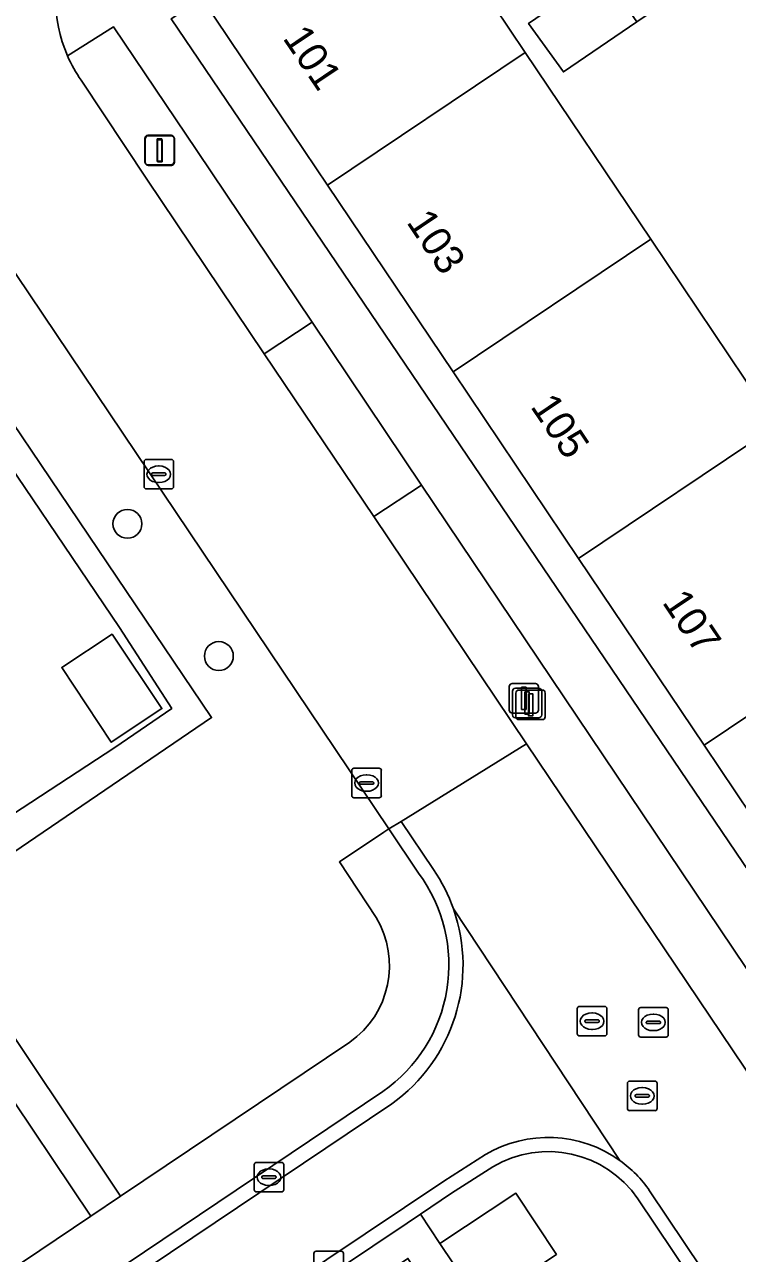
# Model space of a CAD drawing. Extents: x 158793 to 159888, y 384317 to 385256.
# Drawn here: x 159112.15 to 159136.27, y 384672.74 to 384714.36 of the extents above; entities that cross this region are included whole.
import ezdxf

# ---------------------------------------------------------------- set-up
doc = ezdxf.new("R2010")
doc.units = 0
for name, color, linetype in [('IMGEO_Berm_groen', 7, 'Continuous'), ('IMGEO_Boom', 7, 'Continuous'), ('IMGEO_Erf', 7, 'Continuous'), ('IMGEO_Groenvoorziening', 7, 'Continuous'), ('IMGEO_Haag', 7, 'Continuous'), ('IMGEO_Kolk', 7, 'Continuous'), ('IMGEO_Lichtmast', 7, 'Continuous'), ('IMGEO_Pand', 7, 'Continuous'), ('IMGEO_Pand_nummerreeks', 7, 'Continuous'), ('IMGEO_Parkeervlak_halfverhard', 7, 'Continuous'), ('IMGEO_Rijbaan_lokaal_open', 7, 'Continuous'), ('IMGEO_Rioolput', 7, 'Continuous'), ('IMGEO_Voetpad_halfverhard', 7, 'Continuous'), ('IMGEO_Voetpad_open', 7, 'Continuous')]:
    doc.layers.add(name, color=color, linetype=linetype)

msp = doc.modelspace()

# ---------------------------------------------------------------- linework, layer by layer
at = {"layer": 'IMGEO_Berm_groen'}
for points in [[(159115.157, 384714.276), (159113.6, 384713.295)], [(159114.065, 384712.473), (159116.285, 384709.123), (159120.258, 384703.211), (159121.876, 384704.284), (159117.976, 384710.09), (159115.157, 384714.276)], [(159125.586, 384698.761), (159123.965, 384697.697), (159129.137, 384690.002), (159138.056, 384676.732)], [(159141.53, 384675.048), (159141.397, 384675.222), (159125.586, 384698.761)], [(159127.995, 384675.679), (159126.599, 384674.78), (159125.549, 384674.076), (159126.206, 384673.075), (159128.775, 384674.779), (159130.148, 384672.707), (159127.589, 384671.004), (159136.246, 384658.77), (159136.871, 384659.186), (159139.241, 384655.885)], [(159143.015, 384659.487), (159142.977, 384659.569), (159132.904, 384674.594)]]:
    msp.add_lwpolyline(points, dxfattribs=at)
for centre, radius, start, end in [((159117.908, 384715.189), 4.706, 203.7376, 215.2555), ((159129.868, 384672.507), 3.684, 34.5126, 120.5609)]:
    msp.add_arc(centre, radius, start, end, dxfattribs=at)
at = {"layer": 'IMGEO_Boom'}
for centre in [(159115.627, 384697.449), (159118.722, 384692.972)]:
    msp.add_circle(centre, 0.489, dxfattribs=at)
at = {"layer": 'IMGEO_Erf'}
for points in [[(159130.77, 384723.782), (159124.843, 384719.739), (159129.091, 384713.416), (159133.339, 384707.093), (159137.587, 384700.771), (159141.835, 384694.448), (159146.083, 384688.125), (159150.331, 384681.802), (159156.259, 384685.944)], [(159132.872, 384714.449), (159130.387, 384712.756), (159129.203, 384714.398), (159131.723, 384716.125), (159134.243, 384717.853), (159135.378, 384716.157)], [(159113.403, 384692.586), (159115.106, 384693.712), (159116.797, 384691.192), (159115.078, 384690.055)]]:
    msp.add_lwpolyline(points, close=True, dxfattribs=at)
msp.add_lwpolyline([(159108.265, 384685.338), (159115.197, 384689.875), (159117.127, 384691.2), (159115.361, 384693.939), (159105.215, 384708.932)], dxfattribs=at)
at = {"layer": 'IMGEO_Groenvoorziening'}
for points in [[(159103.077, 384713.871), (159105.954, 384709.447), (159118.478, 384690.888), (159108.91, 384684.374), (159115.398, 384674.683), (159123.154, 384679.895)], [(159118.478, 384690.888), (159105.954, 384709.447), (159103.077, 384713.871)], [(159102.092, 384713.443), (159100.643, 384712.514), (159093.526, 384707.69), (159093.829, 384707.184), (159094.623, 384707.728), (159097.156, 384709.402), (159102.429, 384713.049), (159105.215, 384708.932), (159115.361, 384693.939), (159117.127, 384691.2), (159115.197, 384689.875), (159108.265, 384685.338), (159108.91, 384684.374), (159118.478, 384690.888)], [(159124.044, 384684.121), (159122.802, 384686.002), (159124.307, 384687.004), (159124.478, 384687.124), (159108.697, 384710.581), (159107.572, 384712.264)], [(159114.386, 384674.002), (159107.906, 384683.665), (159099.356, 384678.075)], [(159097.742, 384678.578), (159096.312, 384680.64), (159079.482, 384669.508), (159079.569, 384669.376), (159079.588, 384669.39), (159080.687, 384667.744), (159085.364, 384670.862), (159087.614, 384667.53), (159092.976, 384659.587), (159114.386, 384674.002)]]:
    msp.add_lwpolyline(points, dxfattribs=at)
msp.add_lwpolyline([(159131.37, 384663.302), (159134.369, 384658.886), (159130.239, 384656.078), (159130.835, 384655.176), (159135.895, 384658.537), (159136.246, 384658.77), (159127.589, 384671.004), (159127.54, 384671.077), (159126.206, 384673.075), (159125.549, 384674.076), (159125.095, 384673.771), (159120.411, 384670.625), (159120.976, 384669.793), (159125.12, 384672.575), (159130.785, 384664.135), (159126.66, 384661.331), (159127.184, 384660.536)], close=True, dxfattribs=at)
msp.add_arc((159121.324, 384682.487), 3.173, 305.2214, 30.9931, dxfattribs=at)
at = {"layer": 'IMGEO_Haag'}
for points in [[(159118.478, 384690.888), (159105.954, 384709.447), (159103.077, 384713.871)], [(159102.092, 384713.443), (159100.643, 384712.514), (159093.526, 384707.69), (159093.829, 384707.184), (159094.623, 384707.728), (159097.156, 384709.402), (159102.429, 384713.049), (159105.215, 384708.932), (159115.361, 384693.939), (159117.127, 384691.2), (159115.197, 384689.875), (159108.265, 384685.338), (159108.91, 384684.374), (159118.478, 384690.888)]]:
    msp.add_lwpolyline(points, dxfattribs=at)
at = {"layer": 'IMGEO_Kolk'}
for p, q in [((159116.188, 384698.704), (159116.188, 384699.556)), ((159116.263, 384699.63), (159117.115, 384699.63)), ((159117.189, 384699.556), (159117.189, 384698.704)), ((159116.447, 384699.124), (159116.447, 384699.136)), ((159116.49, 384699.173), (159116.888, 384699.173)), ((159116.676, 384699.41), (159116.701, 384699.41)), ((159116.931, 384699.136), (159116.931, 384699.124)), ((159116.885, 384699.087), (159116.487, 384699.087)), ((159116.699, 384698.85), (159116.674, 384698.85)), ((159117.115, 384698.63), (159116.263, 384698.63)), ((159123.295, 384689.171), (159124.147, 384689.171)), ((159123.22, 384688.245), (159123.22, 384689.097)), ((159123.522, 384688.714), (159123.92, 384688.714)), ((159123.708, 384688.951), (159123.733, 384688.951)), ((159124.221, 384689.097), (159124.221, 384688.245)), ((159123.479, 384688.665), (159123.479, 384688.677)), ((159123.917, 384688.628), (159123.519, 384688.628)), ((159123.731, 384688.391), (159123.706, 384688.391)), ((159123.963, 384688.677), (159123.963, 384688.665)), ((159124.147, 384688.171), (159123.295, 384688.171)), ((159119.992, 384675.823), (159120.844, 384675.823)), ((159119.917, 384674.897), (159119.917, 384675.749)), ((159120.405, 384675.603), (159120.43, 384675.603)), ((159120.918, 384675.749), (159120.918, 384674.897)), ((159120.176, 384675.317), (159120.176, 384675.329)), ((159120.614, 384675.28), (159120.216, 384675.28)), ((159120.219, 384675.366), (159120.617, 384675.366)), ((159120.428, 384675.043), (159120.403, 384675.043)), ((159120.66, 384675.329), (159120.66, 384675.317)), ((159120.844, 384674.823), (159119.992, 384674.823)), ((159121.938, 384671.89), (159121.938, 384672.742)), ((159122.013, 384672.816), (159122.865, 384672.816)), ((159122.939, 384672.742), (159122.939, 384671.89))]:
    msp.add_line(p, q, dxfattribs=at)
for points in [[(159116.188, 384698.704), (159116.188, 384699.556)], [(159116.263, 384699.63), (159117.115, 384699.63)], [(159117.189, 384699.556), (159117.189, 384698.704)], [(159117.115, 384698.63), (159116.263, 384698.63)], [(159123.295, 384689.171), (159124.147, 384689.171)], [(159123.22, 384688.245), (159123.22, 384689.097)], [(159124.221, 384689.097), (159124.221, 384688.245)], [(159124.147, 384688.171), (159123.295, 384688.171)], [(159119.992, 384675.823), (159120.844, 384675.823)], [(159119.917, 384674.897), (159119.917, 384675.749)], [(159120.918, 384675.749), (159120.918, 384674.897)], [(159120.844, 384674.823), (159119.992, 384674.823)], [(159121.938, 384671.89), (159121.938, 384672.742)], [(159122.013, 384672.816), (159122.865, 384672.816)], [(159122.939, 384672.742), (159122.939, 384671.89)]]:
    msp.add_lwpolyline(points, dxfattribs=at)
for centre, radius, start, end in [((159116.265, 384699.554), 0.0765, 91.552, 178.448), ((159116.265, 384699.554), 0.0765, 91.552, 178.448), ((159117.113, 384699.554), 0.0765, 1.552, 88.448), ((159117.113, 384699.554), 0.0765, 1.552, 88.448), ((159116.487, 384699.133), 0.0403, 85.8775, 175.7526), ((159116.484, 384699.123), 0.0366, 178.938, 274.7102), ((159116.888, 384699.13), 0.043, 264.8664, 352.4533), ((159116.892, 384699.135), 0.0386, 1.7309, 96.639), ((159116.265, 384698.706), 0.0765, 181.552, 268.448), ((159116.265, 384698.706), 0.0765, 181.552, 268.448), ((159117.113, 384698.706), 0.0765, 271.552, 358.448), ((159117.113, 384698.706), 0.0765, 271.552, 358.448), ((159123.297, 384689.095), 0.0765, 91.552, 178.448), ((159123.297, 384689.095), 0.0765, 91.552, 178.448), ((159124.145, 384689.095), 0.0765, 1.552, 88.448), ((159124.145, 384689.095), 0.0765, 1.552, 88.448), ((159123.519, 384688.674), 0.0403, 85.8775, 175.7526), ((159123.924, 384688.676), 0.0386, 1.7309, 96.639), ((159123.516, 384688.664), 0.0366, 178.938, 274.7102), ((159123.92, 384688.671), 0.043, 264.8664, 352.4533), ((159123.297, 384688.247), 0.0765, 181.552, 268.448), ((159123.297, 384688.247), 0.0765, 181.552, 268.448), ((159124.145, 384688.247), 0.0765, 271.552, 358.448), ((159124.145, 384688.247), 0.0765, 271.552, 358.448), ((159119.994, 384675.747), 0.0765, 91.552, 178.448), ((159119.994, 384675.747), 0.0765, 91.552, 178.448), ((159120.842, 384675.747), 0.0765, 1.552, 88.448), ((159120.842, 384675.747), 0.0765, 1.552, 88.448), ((159120.216, 384675.326), 0.0403, 85.8775, 175.7526), ((159120.213, 384675.316), 0.0366, 178.938, 274.7102), ((159120.617, 384675.323), 0.043, 264.8664, 352.4533), ((159120.621, 384675.328), 0.0386, 1.7309, 96.639), ((159119.994, 384674.899), 0.0765, 181.552, 268.448), ((159119.994, 384674.899), 0.0765, 181.552, 268.448), ((159120.842, 384674.899), 0.0765, 271.552, 358.448), ((159120.842, 384674.899), 0.0765, 271.552, 358.448), ((159122.015, 384672.74), 0.0765, 91.552, 178.448), ((159122.015, 384672.74), 0.0765, 91.552, 178.448), ((159122.863, 384672.74), 0.0765, 1.552, 88.448), ((159122.863, 384672.74), 0.0765, 1.552, 88.448)]:
    msp.add_arc(centre, radius, start, end, dxfattribs=at)
for centre, major_axis, ratio, start_param, end_param in [((159116.675, 384699.13), (-0.387, 0.002), 0.722429, 4.712389, 7.853982), ((159116.7, 384699.13), (-0.39, 0.002), 0.717154, 1.570796, 4.712389), ((159123.707, 384688.671), (-0.387, 0.002), 0.722429, 4.712389, 7.853982), ((159123.732, 384688.671), (-0.39, 0.002), 0.717154, 1.570796, 4.712389), ((159120.404, 384675.323), (-0.387, 0.002), 0.722429, 4.712389, 7.853982), ((159120.429, 384675.323), (-0.39, 0.002), 0.717154, 1.570796, 4.712389)]:
    msp.add_ellipse(centre, major_axis=major_axis, ratio=ratio, start_param=start_param, end_param=end_param, dxfattribs=at)
at = {"layer": 'IMGEO_Lichtmast'}
for p, q in [((159116.216, 384709.712), (159116.216, 384710.512)), ((159116.216, 384710.512), (159116.216, 384709.712)), ((159116.228, 384709.684), (159116.228, 384710.484)), ((159116.228, 384710.484), (159116.228, 384709.684)), ((159116.316, 384710.612), (159117.106, 384710.612)), ((159117.106, 384710.612), (159116.316, 384710.612)), ((159116.328, 384710.584), (159117.118, 384710.584)), ((159117.118, 384710.584), (159116.328, 384710.584)), ((159117.206, 384710.512), (159117.206, 384709.712)), ((159117.206, 384709.712), (159117.206, 384710.512)), ((159117.218, 384710.484), (159117.218, 384709.684)), ((159117.218, 384709.684), (159117.218, 384710.484)), ((159117.106, 384709.612), (159116.316, 384709.612)), ((159116.316, 384709.612), (159117.106, 384709.612)), ((159117.118, 384709.584), (159116.328, 384709.584)), ((159116.328, 384709.584), (159117.118, 384709.584)), ((159128.65, 384692.041), (159129.44, 384692.041)), ((159129.44, 384692.041), (159128.65, 384692.041)), ((159128.55, 384691.141), (159128.55, 384691.941)), ((159128.55, 384691.941), (159128.55, 384691.141)), ((159128.66, 384690.98), (159128.66, 384691.78)), ((159128.66, 384691.78), (159128.66, 384690.98)), ((159128.76, 384691.88), (159129.55, 384691.88)), ((159129.55, 384691.88), (159128.76, 384691.88)), ((159128.778, 384690.919), (159128.778, 384691.719)), ((159128.778, 384691.719), (159128.778, 384690.919)), ((159128.878, 384691.819), (159129.668, 384691.819)), ((159129.668, 384691.819), (159128.878, 384691.819)), ((159129.54, 384691.941), (159129.54, 384691.141)), ((159129.54, 384691.141), (159129.54, 384691.941)), ((159129.65, 384691.78), (159129.65, 384690.98)), ((159129.65, 384690.98), (159129.65, 384691.78)), ((159129.768, 384691.719), (159129.768, 384690.919)), ((159129.768, 384690.919), (159129.768, 384691.719)), ((159129.44, 384691.041), (159128.65, 384691.041)), ((159128.65, 384691.041), (159129.44, 384691.041)), ((159129.55, 384690.88), (159128.76, 384690.88)), ((159128.76, 384690.88), (159129.55, 384690.88)), ((159129.668, 384690.819), (159128.878, 384690.819)), ((159128.878, 384690.819), (159129.668, 384690.819))]:
    msp.add_line(p, q, dxfattribs=at)
for points in [[(159116.636, 384710.487), (159116.786, 384710.487), (159116.786, 384709.737), (159116.636, 384709.737), (159116.636, 384710.487)], [(159116.648, 384710.459), (159116.798, 384710.459), (159116.798, 384709.709), (159116.648, 384709.709), (159116.648, 384710.459)], [(159128.97, 384691.916), (159129.12, 384691.916), (159129.12, 384691.166), (159128.97, 384691.166), (159128.97, 384691.916)], [(159129.08, 384691.755), (159129.23, 384691.755), (159129.23, 384691.005), (159129.08, 384691.005), (159129.08, 384691.755)], [(159129.198, 384691.694), (159129.348, 384691.694), (159129.348, 384690.944), (159129.198, 384690.944), (159129.198, 384691.694)]]:
    msp.add_lwpolyline(points, dxfattribs=at)
for centre, start, end in [((159116.316, 384710.512), 90, 180), ((159116.316, 384710.512), 90, 180), ((159116.328, 384710.484), 90, 180), ((159116.328, 384710.484), 90, 180), ((159117.106, 384710.512), 0, 90), ((159117.106, 384710.512), 360, 90), ((159117.118, 384710.484), 0, 90), ((159117.118, 384710.484), 360, 90), ((159116.316, 384709.712), 180, 270), ((159116.316, 384709.712), 180, 270), ((159116.328, 384709.684), 180, 270), ((159116.328, 384709.684), 180, 270), ((159117.106, 384709.712), 270, 0), ((159117.106, 384709.712), 270, 0), ((159117.118, 384709.684), 270, 0), ((159117.118, 384709.684), 270, 0), ((159128.65, 384691.941), 90, 180), ((159128.65, 384691.941), 90, 180), ((159129.44, 384691.941), 0, 90), ((159129.44, 384691.941), 360, 90), ((159128.76, 384691.78), 90, 180), ((159128.76, 384691.78), 90, 180), ((159128.878, 384691.719), 90, 180), ((159128.878, 384691.719), 90, 180), ((159129.55, 384691.78), 0, 90), ((159129.55, 384691.78), 360, 90), ((159129.668, 384691.719), 0, 90), ((159129.668, 384691.719), 360, 90), ((159128.65, 384691.141), 180, 270), ((159128.65, 384691.141), 180, 270), ((159128.76, 384690.98), 180, 270), ((159128.76, 384690.98), 180, 270), ((159128.878, 384690.919), 180, 270), ((159128.878, 384690.919), 180, 270), ((159129.44, 384691.141), 270, 0), ((159129.44, 384691.141), 270, 0), ((159129.55, 384690.98), 270, 0), ((159129.55, 384690.98), 270, 0), ((159129.668, 384690.919), 270, 0), ((159129.668, 384690.919), 270, 0)]:
    msp.add_arc(centre, 0.1, start, end, dxfattribs=at)
at = {"layer": 'IMGEO_Pand'}
for points in [[(159124.843, 384719.739), (159118.154, 384715.239), (159120.427, 384711.857), (159122.4, 384708.921), (159129.091, 384713.416)], [(159131.723, 384716.125), (159129.203, 384714.398), (159130.387, 384712.756), (159132.872, 384714.449)], [(159129.091, 384713.416), (159122.4, 384708.921), (159126.649, 384702.599), (159133.339, 384707.093)], [(159133.339, 384707.093), (159126.649, 384702.599), (159130.898, 384696.277), (159137.587, 384700.771)], [(159137.587, 384700.771), (159130.898, 384696.277), (159135.147, 384689.954), (159141.835, 384694.448)], [(159141.835, 384694.448), (159135.147, 384689.954), (159139.396, 384683.632), (159146.083, 384688.125)], [(159115.106, 384693.712), (159113.403, 384692.586), (159115.078, 384690.055), (159116.797, 384691.192)], [(159128.775, 384674.779), (159126.206, 384673.075), (159127.54, 384671.077), (159127.589, 384671.004), (159130.148, 384672.707)]]:
    msp.add_lwpolyline(points, close=True, dxfattribs=at)
at = {"layer": 'IMGEO_Parkeervlak_halfverhard'}
msp.add_lwpolyline([(159121.876, 384704.284), (159120.258, 384703.211), (159123.965, 384697.697), (159125.586, 384698.761)], close=True, dxfattribs=at)
at = {"layer": 'IMGEO_Rijbaan_lokaal_open'}
for points in [[(159107.572, 384712.264), (159108.697, 384710.581), (159124.478, 384687.124), (159124.888, 384687.365), (159129.137, 384690.002), (159123.965, 384697.697), (159120.258, 384703.211), (159116.285, 384709.123), (159114.065, 384712.473)], [(159138.056, 384676.732), (159129.137, 384690.002), (159124.888, 384687.365), (159125.988, 384685.741)], [(159125.481, 384685.621), (159124.478, 384687.124), (159124.307, 384687.004), (159122.802, 384686.002), (159124.044, 384684.121)], [(159125.988, 384685.741), (159124.888, 384687.365), (159124.478, 384687.124), (159125.481, 384685.621)], [(159132.296, 384675.89), (159126.66, 384684.409)], [(159126.66, 384684.409), (159132.296, 384675.89)], [(159123.154, 384679.895), (159115.398, 384674.683), (159114.386, 384674.002), (159092.976, 384659.587), (159091.396, 384658.524), (159089.164, 384657.021), (159083.762, 384653.406), (159076.201, 384648.352), (159076.202, 384648.351), (159079.779, 384642.984), (159078.044, 384641.798), (159072.82, 384638.349), (159064.596, 384632.772)], [(159124.276, 384678.229), (159083.889, 384651.05), (159084.148, 384650.648), (159124.574, 384677.811)], [(159124.574, 384677.811), (159084.148, 384650.648), (159083.889, 384651.05), (159124.276, 384678.229)], [(159115.57, 384667.981), (159126.067, 384652.043), (159130.227, 384654.776), (159119.718, 384670.754), (159126.339, 384675.184), (159127.743, 384676.087)], [(159127.743, 384676.087), (159126.339, 384675.184), (159119.718, 384670.754), (159130.227, 384654.776), (159130.835, 384655.176), (159130.239, 384656.078), (159127.184, 384660.536), (159126.66, 384661.331), (159120.976, 384669.793), (159120.411, 384670.625), (159125.095, 384673.771), (159125.549, 384674.076), (159126.599, 384674.78), (159127.995, 384675.679)], [(159132.904, 384674.594), (159142.977, 384659.569), (159151.786, 384646.421), (159151.816, 384646.386), (159153.659, 384643.618), (159153.675, 384643.594), (159162.493, 384630.457), (159163.415, 384629.083), (159169.136, 384620.552)], [(159169.474, 384620.932), (159143.376, 384659.836), (159133.301, 384674.864)], [(159133.301, 384674.864), (159143.376, 384659.836), (159169.474, 384620.932)]]:
    msp.add_lwpolyline(points, dxfattribs=at)
for centre, radius, start, end in [((159117.927, 384715.199), 4.727, 154.6119, 203.7558), ((159117.908, 384715.189), 4.706, 203.7376, 215.2555), ((159121.287, 384682.511), 5.222, 304.9236, 36.5593), ((159121.287, 384682.511), 5.222, 304.9236, 36.5593), ((159121.203, 384682.491), 5.784, 19.3617, 34.1806), ((159121.203, 384682.491), 5.784, 19.3617, 34.1806), ((159121.324, 384682.487), 3.173, 305.2214, 30.9931), ((159121.223, 384682.499), 5.763, 305.5582, 19.3524), ((159121.223, 384682.499), 5.763, 305.5582, 19.3524), ((159129.869, 384672.507), 4.164, 54.3427, 120.7022), ((159129.869, 384672.507), 4.164, 54.3427, 120.7022), ((159129.868, 384672.507), 3.684, 34.5126, 120.5609), ((159129.877, 384672.516), 4.151, 34.4467, 54.3685), ((159129.877, 384672.516), 4.151, 34.4467, 54.3685)]:
    msp.add_arc(centre, radius, start, end, dxfattribs=at)
at = {"layer": 'IMGEO_Rioolput'}
for p, q in [((159130.854, 384680.181), (159130.854, 384681.033)), ((159130.929, 384681.107), (159131.781, 384681.107)), ((159131.342, 384680.887), (159131.367, 384680.887)), ((159131.855, 384681.033), (159131.855, 384680.181)), ((159132.93, 384680.14), (159132.93, 384680.992)), ((159133.005, 384681.066), (159133.857, 384681.066)), ((159133.418, 384680.846), (159133.443, 384680.846)), ((159133.931, 384680.992), (159133.931, 384680.14)), ((159131.113, 384680.601), (159131.113, 384680.613)), ((159131.551, 384680.564), (159131.153, 384680.564)), ((159131.156, 384680.65), (159131.554, 384680.65)), ((159131.597, 384680.613), (159131.597, 384680.601)), ((159133.189, 384680.56), (159133.189, 384680.572)), ((159133.627, 384680.523), (159133.229, 384680.523)), ((159133.232, 384680.609), (159133.63, 384680.609)), ((159133.673, 384680.572), (159133.673, 384680.56)), ((159131.781, 384680.107), (159130.929, 384680.107)), ((159131.365, 384680.327), (159131.34, 384680.327)), ((159133.857, 384680.066), (159133.005, 384680.066)), ((159133.441, 384680.286), (159133.416, 384680.286)), ((159132.552, 384677.651), (159132.552, 384678.503)), ((159132.627, 384678.577), (159133.479, 384678.577)), ((159133.04, 384678.357), (159133.065, 384678.357)), ((159133.553, 384678.503), (159133.553, 384677.651)), ((159132.811, 384678.071), (159132.811, 384678.083)), ((159133.249, 384678.034), (159132.851, 384678.034)), ((159132.854, 384678.12), (159133.252, 384678.12)), ((159133.295, 384678.083), (159133.295, 384678.071)), ((159133.479, 384677.577), (159132.627, 384677.577)), ((159133.063, 384677.797), (159133.038, 384677.797))]:
    msp.add_line(p, q, dxfattribs=at)
for points in [[(159130.854, 384680.181), (159130.854, 384681.033)], [(159130.929, 384681.107), (159131.781, 384681.107)], [(159131.855, 384681.033), (159131.855, 384680.181)], [(159132.93, 384680.14), (159132.93, 384680.992)], [(159133.005, 384681.066), (159133.857, 384681.066)], [(159133.931, 384680.992), (159133.931, 384680.14)], [(159131.781, 384680.107), (159130.929, 384680.107)], [(159133.857, 384680.066), (159133.005, 384680.066)], [(159132.552, 384677.651), (159132.552, 384678.503)], [(159132.627, 384678.577), (159133.479, 384678.577)], [(159133.553, 384678.503), (159133.553, 384677.651)], [(159133.479, 384677.577), (159132.627, 384677.577)]]:
    msp.add_lwpolyline(points, dxfattribs=at)
for centre, radius, start, end in [((159130.931, 384681.031), 0.0765, 91.552, 178.448), ((159130.931, 384681.031), 0.0765, 91.552, 178.448), ((159131.779, 384681.031), 0.0765, 1.552, 88.448), ((159131.779, 384681.031), 0.0765, 1.552, 88.448), ((159133.007, 384680.99), 0.0765, 91.552, 178.448), ((159133.007, 384680.99), 0.0765, 91.552, 178.448), ((159133.855, 384680.99), 0.0765, 1.552, 88.448), ((159133.855, 384680.99), 0.0765, 1.552, 88.448), ((159131.153, 384680.61), 0.0403, 85.8775, 175.7526), ((159131.15, 384680.6), 0.0366, 178.938, 274.7102), ((159131.554, 384680.607), 0.043, 264.8664, 352.4533), ((159131.558, 384680.612), 0.0386, 1.7309, 96.639), ((159133.229, 384680.569), 0.0403, 85.8775, 175.7526), ((159133.226, 384680.559), 0.0366, 178.938, 274.7102), ((159133.63, 384680.566), 0.043, 264.8664, 352.4533), ((159133.634, 384680.571), 0.0386, 1.7309, 96.639), ((159130.931, 384680.183), 0.0765, 181.552, 268.448), ((159130.931, 384680.183), 0.0765, 181.552, 268.448), ((159131.779, 384680.183), 0.0765, 271.552, 358.448), ((159131.779, 384680.183), 0.0765, 271.552, 358.448), ((159133.007, 384680.142), 0.0765, 181.552, 268.448), ((159133.007, 384680.142), 0.0765, 181.552, 268.448), ((159133.855, 384680.142), 0.0765, 271.552, 358.448), ((159133.855, 384680.142), 0.0765, 271.552, 358.448), ((159132.629, 384678.501), 0.0765, 91.552, 178.448), ((159132.629, 384678.501), 0.0765, 91.552, 178.448), ((159133.477, 384678.501), 0.0765, 1.552, 88.448), ((159133.477, 384678.501), 0.0765, 1.552, 88.448), ((159132.851, 384678.08), 0.0403, 85.8775, 175.7526), ((159132.848, 384678.07), 0.0366, 178.938, 274.7102), ((159133.252, 384678.077), 0.043, 264.8664, 352.4533), ((159133.256, 384678.082), 0.0386, 1.7309, 96.639), ((159132.629, 384677.653), 0.0765, 181.552, 268.448), ((159132.629, 384677.653), 0.0765, 181.552, 268.448), ((159133.477, 384677.653), 0.0765, 271.552, 358.448), ((159133.477, 384677.653), 0.0765, 271.552, 358.448)]:
    msp.add_arc(centre, radius, start, end, dxfattribs=at)
for centre, major_axis, ratio, start_param, end_param in [((159131.341, 384680.607), (-0.387, 0.002), 0.722429, 4.712389, 7.853982), ((159131.366, 384680.607), (-0.39, 0.002), 0.717154, 1.570796, 4.712389), ((159133.417, 384680.566), (-0.387, 0.002), 0.722429, 4.712389, 7.853982), ((159133.442, 384680.566), (-0.39, 0.002), 0.717154, 1.570796, 4.712389), ((159133.039, 384678.077), (-0.387, 0.002), 0.722429, 4.712389, 7.853982), ((159133.064, 384678.077), (-0.39, 0.002), 0.717154, 1.570796, 4.712389)]:
    msp.add_ellipse(centre, major_axis=major_axis, ratio=ratio, start_param=start_param, end_param=end_param, dxfattribs=at)
at = {"layer": 'IMGEO_Voetpad_halfverhard'}
msp.add_lwpolyline([(159108.91, 384684.374), (159107.906, 384683.665), (159114.386, 384674.002), (159115.398, 384674.683)], close=True, dxfattribs=at)
at = {"layer": 'IMGEO_Voetpad_open'}
msp.add_lwpolyline([(159130.898, 384696.277), (159126.649, 384702.599), (159122.4, 384708.921), (159120.427, 384711.857), (159118.154, 384715.239), (159117.11, 384714.557), (159142.742, 384676.698), (159143.648, 384677.306), (159139.396, 384683.632), (159135.147, 384689.954)], close=True, dxfattribs=at)
for points in [[(159143.234, 384675.735), (159144.25, 384676.451), (159143.648, 384677.306), (159142.742, 384676.698), (159117.11, 384714.557)], [(159113.6, 384713.295), (159115.157, 384714.276), (159117.976, 384710.09), (159121.876, 384704.284), (159125.586, 384698.761), (159141.397, 384675.222), (159141.53, 384675.048)]]:
    msp.add_lwpolyline(points, dxfattribs=at)
msp.add_arc((159117.927, 384715.199), 4.727, 154.6119, 203.7558, dxfattribs=at)

# ---------------------------------------------------------------- texts
at = {"layer": 'IMGEO_Pand_nummerreeks'}
for s, p in [('101', (159120.862, 384713.899)), ('103', (159125.051, 384707.665)), ('105', (159129.247, 384701.422)), ('107', (159133.705, 384694.79))]:
    msp.add_text(s, height=1, rotation=303.9017, dxfattribs=at).set_placement(p)

doc.saveas('drawing.dxf')
